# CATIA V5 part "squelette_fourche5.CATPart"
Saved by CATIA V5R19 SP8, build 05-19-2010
Part number: squelette_fourche5
Bounding box of the stored display mesh (mm): x 10 to 30, y -46.648 to 0, z 0 to 0
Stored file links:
  G:\EU_thinkMotion\CFAO_2010\MMS_groupe2\MMS_groupe2\A reprendre\jcauchy\squelette_fourche5.CATPart
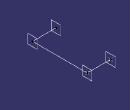
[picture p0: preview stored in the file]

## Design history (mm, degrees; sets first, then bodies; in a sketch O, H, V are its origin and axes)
Parameters
  Longueurfixation_fourche5 = 20 mm
  separationroue_fourche5 = 64 mm
  separationfixation_fourche5 = 120 mm
Set1
  Point1: (10 {= 30mm-Longueurfixation_fourche5}, 0, 0)
  Point2: (30, 0, 0)
  Line1: type PtPt, FirstPoint Point2, SecondPoint Point1
  Point3: type OnCurve, Support Line1, RefPoint Point1, Length -20 {= -Longueurfixation_fourche5}
  Plane1: type Normal, Curve Line1, RefPoint Point1
  Plane2: type Normal, Curve Line1, RefPoint Point2
  Line2: type Angle, RefPoint Point3, Curve Line1, Support xy-plane, Start 0, End 46.6476 {= sqrt((separationroue_fourche5 -(separationfixation_fourche5 -(separationroue_fourche5 +separationroue_fourche5 /2)))*(separationroue_fourche5 -(separationfixation_fourche5 -(separationroue_fourche5 +separationroue_fourche5 /2)))+(separationfixation_fourche5 -(separationroue_fourche5 +separationroue_fourche5 /2))*(separationfixation_fourche5 -(separationroue_fourche5 +separationroue_fourche5 /2))*tan(45deg)*tan(45deg))}, Angle 90
  Line3: type Angle, RefPoint vertex of Line2, Curve Line2, Support xy-plane, Start -20 {= -Longueurfixation_fourche5}, End 0, Angle 90
  Plane3: type Normal, Curve Line3, RefPoint vertex of Line3
  Plane4: type Normal, Curve Line3, RefPoint vertex of Line3
Body1 (main body)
